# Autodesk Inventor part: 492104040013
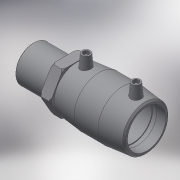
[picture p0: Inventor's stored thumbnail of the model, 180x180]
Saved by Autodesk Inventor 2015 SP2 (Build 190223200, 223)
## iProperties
Created: 2017-06
Part Number: 492104040013
Material: Generic
Description: PLASSON Male Transition Coupler 40 x 1.1/4"
Document SubType Name: Modeling
Designer: KIM
Mass: 160.277 g
Surface Area: 446.355 cm^2
Volume: 160.277 cm^3
Density: 1 g/cm^3
Appearance: Default
Author: KIM
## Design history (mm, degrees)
derived "492104.ipt"
feature "Solid1::492104.ipt"
tag "TaggingFeature1"
body "Solid1"
other parameters: "d0" = 97, "d2" = 56, "d3" = 47, "d4" = 32.33333, "d5" = 50.4, "d6" = 38, "d8" = 168 deg, "d10" = 18.8, "d11" = 6.26667, "d29" = 46, "d30" = 14, "d31" = 33.95, "d34" = 5 deg, "d41" = 4, "d42" = 14, "d43" = 0, "d48" = 3, "d49" = 0, "d57" = 29, "d58" = 41.91, "d59" = 33.528, "d60" = 32.4, "d61" = 56, "d62" = 0.8382, "d65" = 1.68, "d70" = 0.1, "d71" = 36, "d72" = 9, "d73" = 18.8, "d75" = 0, "L_" = 133, "L_1" = 47, "D_1" = 56, "A_" = 46, "d_2" = 12, "L_2" = 36, "D_" = 29, "R_" = 41.91
